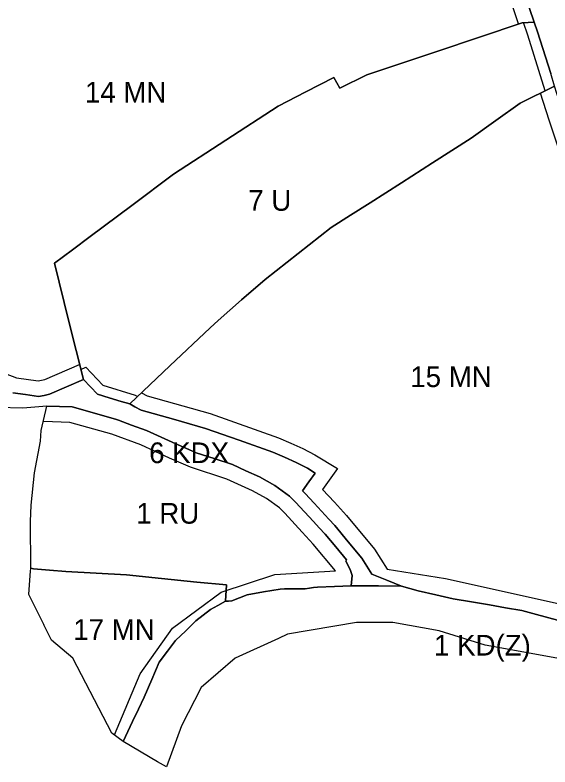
# Model space of a CAD drawing. Extents: x 7423691 to 7425475, y 5552085 to 5554331.
# Drawn here: x 7424385.3 to 7424592.3, y 5552093.8 to 5552384.7 of the extents above; entities that cross this region are included whole.
import ezdxf

# ---------------------------------------------------------------- set-up
doc = ezdxf.new("R2010")
doc.units = 0
for name, color, linetype in [('linia_zabudowy_nieprzekraczalna', 7, 'Continuous'), ('linie_rozgraniczajace', 7, 'Continuous'), ('oznaczenia_przeznaczen', 7, 'Continuous')]:
    doc.layers.add(name, color=color, linetype=linetype)

msp = doc.modelspace()

# ---------------------------------------------------------------- linework, layer by layer
at = {"layer": 'linia_zabudowy_nieprzekraczalna'}
for points in [[(7424580.08, 5552381.26), (7424571.92, 5552405.53), (7424568.75, 5552420), (7424566.65, 5552434.46), (7424566.31, 5552447.41)], [(7424590.45, 5552355.4), (7424583.65, 5552376.93), (7424582.03, 5552381.75)], [(7424597.86, 5552326.15), (7424591.95, 5552344), (7424588.63, 5552354.51)], [(7424283.11, 5552322.72), (7424290.92, 5552313.42), (7424297.88, 5552305.19), (7424302.65, 5552302.46), (7424313.35, 5552292.4), (7424329.92, 5552277.7), (7424344.76, 5552265.77), (7424358.71, 5552257.06), (7424378.55, 5552246.99), (7424385.8, 5552244.36), (7424394.2, 5552243.19), (7424396.85, 5552243.7), (7424410.23, 5552249.51)], [(7424410.72, 5552247.54), (7424412.64, 5552248.38), (7424419.3, 5552241.49), (7424431.7, 5552237.64), (7424432.69, 5552237.1)], [(7424434.22, 5552238.55), (7424436.36, 5552237.4), (7424460.83, 5552230.47), (7424487.2, 5552221.15), (7424491.95, 5552219.02), (7424496.63, 5552216.92), (7424501.31, 5552214.58), (7424510.07, 5552209.17), (7424504.24, 5552201.15), (7424508.89, 5552196.17), (7424513.53, 5552191.05), (7424524.32, 5552178.07), (7424529.22, 5552170.29), (7424551.84, 5552166.71), (7424604.77, 5552154.87)], [(7424423.7, 5552106.15), (7424433.65, 5552129.8), (7424446.15, 5552147.47), (7424465.09, 5552161.34), (7424485.81, 5552168.18), (7424509.22, 5552169.64), (7424500.69, 5552179.91), (7424496.38, 5552184.66), (7424489.61, 5552191.91), (7424487.56, 5552193.98), (7424482.6, 5552197.61), (7424477.2, 5552200.61), (7424467.19, 5552205.15), (7424453.21, 5552209.71), (7424444.98, 5552213.27), (7424433.89, 5552218.33), (7424422.67, 5552222.46), (7424406.49, 5552227.07), (7424396.44, 5552227.36)]]:
    msp.add_lwpolyline(points, dxfattribs=at)
at = {"layer": 'linie_rozgraniczajace'}
for points in [[(7424582.58, 5552392.65), (7424586.19, 5552381.92), (7424581.46, 5552381.72), (7424564.97, 5552376.16), (7424548.48, 5552370.59), (7424534.94, 5552366.09), (7424521.41, 5552361.59), (7424510.91, 5552356.36), (7424508.62, 5552360.49), (7424497.84, 5552354.96), (7424487.05, 5552349.43), (7424466.85, 5552336.28), (7424446.64, 5552323.12), (7424430.51, 5552311.05), (7424414.38, 5552298.99), (7424407.45, 5552293.8), (7424400.52, 5552288.62), (7424406.11, 5552266.11), (7424411.7, 5552243.61), (7424405.17, 5552240.77), (7424398.64, 5552237.93), (7424396.5, 5552237.52), (7424394.36, 5552237.11), (7424389.35, 5552237.81), (7424384.35, 5552238.5)], [(7424625.63, 5552277.57), (7424621.01, 5552289.31), (7424617.02, 5552298.21), (7424613.04, 5552307.12), (7424610.69, 5552312.66), (7424608.35, 5552318.19), (7424605.89, 5552323.3), (7424603.43, 5552328.4), (7424600.55, 5552337.13), (7424597.66, 5552345.85), (7424594.08, 5552357.17), (7424592.55, 5552362.01), (7424587.45, 5552378.17), (7424586.19, 5552381.92), (7424582.58, 5552392.65)], [(7424594.08, 5552357.17), (7424580.69, 5552350.62), (7424571.25, 5552343.86), (7424561.82, 5552337.09), (7424554.34, 5552332.32), (7424546.87, 5552327.54), (7424534.75, 5552319.8), (7424522.64, 5552312.06), (7424515.1, 5552307.25), (7424507.57, 5552302.44), (7424494.83, 5552292.42), (7424482.09, 5552282.4), (7424472.96, 5552274.44), (7424463.83, 5552266.48), (7424460.82, 5552263.67), (7424445.22, 5552248.94), (7424429.63, 5552234.21), (7424426.31, 5552235.2), (7424421.73, 5552236.58), (7424417.16, 5552237.95), (7424414.43, 5552240.78), (7424411.7, 5552243.61), (7424406.11, 5552266.11), (7424400.52, 5552288.62), (7424407.45, 5552293.8), (7424414.38, 5552298.99), (7424430.51, 5552311.05), (7424446.64, 5552323.12), (7424466.85, 5552336.28), (7424487.05, 5552349.43), (7424497.84, 5552354.96), (7424508.62, 5552360.49), (7424510.91, 5552356.36), (7424521.41, 5552361.59), (7424534.94, 5552366.09), (7424548.48, 5552370.59), (7424564.97, 5552376.16), (7424581.46, 5552381.72), (7424586.19, 5552381.92), (7424587.45, 5552378.17), (7424592.55, 5552362.01)], [(7424595.13, 5552150.56), (7424586.99, 5552152.73), (7424584.17, 5552153.48), (7424581.36, 5552154.23), (7424575.11, 5552155.36), (7424568.87, 5552156.5), (7424561.87, 5552157.66), (7424554.86, 5552158.81), (7424548.08, 5552160.38), (7424541.3, 5552161.95), (7424538.07, 5552162.85), (7424534.84, 5552163.75), (7424529.1, 5552166.04), (7424523.36, 5552168.32), (7424519.45, 5552174.54), (7424514.23, 5552180.83), (7424509, 5552187.12), (7424506.74, 5552189.61), (7424501.01, 5552195.82), (7424497.53, 5552199.54), (7424496.44, 5552200.63), (7424498.93, 5552204.05), (7424501.41, 5552207.46), (7424498.38, 5552209.33), (7424494.06, 5552211.5), (7424489.49, 5552213.55), (7424484.97, 5552215.57), (7424471.99, 5552220.16), (7424459.02, 5552224.75), (7424446.55, 5552228.28), (7424434.09, 5552231.8), (7424431.66, 5552233.11), (7424429.63, 5552234.21), (7424445.22, 5552248.94), (7424460.82, 5552263.67), (7424463.83, 5552266.48), (7424472.96, 5552274.44), (7424482.09, 5552282.4), (7424494.83, 5552292.42), (7424507.57, 5552302.44), (7424515.1, 5552307.25), (7424522.64, 5552312.06), (7424534.75, 5552319.8), (7424546.87, 5552327.54), (7424554.34, 5552332.32), (7424561.82, 5552337.09), (7424571.25, 5552343.86), (7424580.69, 5552350.62), (7424594.08, 5552357.17)], [(7424384.35, 5552238.5), (7424389.35, 5552237.81), (7424394.36, 5552237.11), (7424396.5, 5552237.52), (7424398.64, 5552237.93), (7424405.17, 5552240.77), (7424411.7, 5552243.61), (7424414.43, 5552240.78), (7424417.16, 5552237.95), (7424421.73, 5552236.58), (7424426.31, 5552235.2), (7424429.63, 5552234.21), (7424431.66, 5552233.11), (7424434.09, 5552231.8), (7424446.55, 5552228.28), (7424459.02, 5552224.75), (7424471.99, 5552220.16), (7424484.97, 5552215.57), (7424489.49, 5552213.55), (7424494.06, 5552211.5), (7424498.38, 5552209.33), (7424501.41, 5552207.46), (7424498.93, 5552204.05), (7424496.44, 5552200.63), (7424497.53, 5552199.54), (7424501.01, 5552195.82), (7424506.74, 5552189.61), (7424509, 5552187.12), (7424514.23, 5552180.83), (7424519.45, 5552174.54), (7424523.36, 5552168.32), (7424529.1, 5552166.04), (7424534.84, 5552163.75), (7424525.92, 5552163.82), (7424517, 5552163.89), (7424515.3, 5552163.82), (7424515.72, 5552167.87), (7424514.93, 5552170.19), (7424513.21, 5552173.32), (7424513.5, 5552173.88), (7424509.36, 5552178.86), (7424505.22, 5552183.84), (7424503.01, 5552186.28), (7424500.8, 5552188.72), (7424493.81, 5552196.2), (7424491.48, 5552198.54), (7424485.84, 5552202.67), (7424482.87, 5552204.32), (7424479.9, 5552205.97), (7424474.63, 5552208.36), (7424469.36, 5552210.75), (7424462.35, 5552213.04), (7424455.34, 5552215.32), (7424451.38, 5552217.04), (7424447.46, 5552218.74), (7424436.17, 5552223.88), (7424430.35, 5552226.02), (7424425.29, 5552227.89), (7424424.53, 5552228.16), (7424415.97, 5552230.6), (7424407.41, 5552233.04), (7424397.53, 5552233.33), (7424388.34, 5552232.59), (7424378.48, 5552232.85)], [(7424427.06, 5552103.61), (7424428.91, 5552107.49), (7424430.75, 5552111.36), (7424433, 5552116.08), (7424435.25, 5552120.81), (7424438.17, 5552127.57), (7424441.09, 5552134.34), (7424444.21, 5552138.51), (7424447.34, 5552142.68), (7424451.3, 5552146.48), (7424455.26, 5552150.28), (7424458.05, 5552152.49), (7424460.85, 5552154.7), (7424463.69, 5552156.27), (7424466.66, 5552157.85), (7424467.82, 5552157.91), (7424469.11, 5552157.98), (7424472.11, 5552159.13), (7424475.11, 5552160.29), (7424481.47, 5552161.45), (7424487.83, 5552162.6), (7424489.53, 5552162.64), (7424491.24, 5552162.67), (7424491.68, 5552162.62), (7424494.59, 5552162.64), (7424496.41, 5552162.65), (7424497.49, 5552162.66), (7424499.15, 5552162.94), (7424500.8, 5552163.23), (7424502.36, 5552163.29), (7424508.9, 5552163.56), (7424515.3, 5552163.82), (7424517, 5552163.89), (7424525.92, 5552163.82), (7424534.84, 5552163.75), (7424538.07, 5552162.85), (7424541.3, 5552161.95), (7424548.08, 5552160.38), (7424554.86, 5552158.81), (7424561.87, 5552157.66), (7424568.87, 5552156.5), (7424575.11, 5552155.36), (7424581.36, 5552154.23), (7424584.17, 5552153.48), (7424586.99, 5552152.73), (7424595.13, 5552150.56)], [(7424664.3, 5552112.25), (7424650.8, 5552112.27), (7424640.17, 5552118.07), (7424622.53, 5552125.65), (7424599.18, 5552135.12), (7424567.14, 5552140.87), (7424549.35, 5552146.45), (7424531.46, 5552149.64), (7424517.45, 5552149.68), (7424490.76, 5552145.07), (7424487.25, 5552143.48), (7424470.4, 5552135.88), (7424457.35, 5552124.46), (7424449.66, 5552109.7), (7424443.85, 5552093.75), (7424440.45, 5552095.75), (7424427.06, 5552103.61)]]:
    msp.add_lwpolyline(points, dxfattribs=at)
for points in [[(7424391.34, 5552170.61), (7424391.22, 5552188.71), (7424391.55, 5552194.98), (7424392.82, 5552207.5), (7424395.06, 5552219.76), (7424395.39, 5552223.99), (7424397.53, 5552233.33), (7424407.41, 5552233.04), (7424415.97, 5552230.6), (7424424.53, 5552228.16), (7424425.29, 5552227.89), (7424430.35, 5552226.02), (7424436.17, 5552223.88), (7424447.46, 5552218.74), (7424451.38, 5552217.04), (7424455.34, 5552215.32), (7424462.35, 5552213.04), (7424469.36, 5552210.75), (7424474.63, 5552208.36), (7424479.9, 5552205.97), (7424482.87, 5552204.32), (7424485.84, 5552202.67), (7424491.48, 5552198.54), (7424493.81, 5552196.2), (7424500.8, 5552188.72), (7424503.01, 5552186.28), (7424505.22, 5552183.84), (7424509.36, 5552178.86), (7424513.5, 5552173.88), (7424513.21, 5552173.32), (7424514.93, 5552170.19), (7424515.72, 5552167.87), (7424515.3, 5552163.82), (7424508.9, 5552163.56), (7424502.36, 5552163.29), (7424500.8, 5552163.23), (7424499.15, 5552162.94), (7424497.49, 5552162.66), (7424496.41, 5552162.65), (7424494.59, 5552162.64), (7424491.68, 5552162.62), (7424491.24, 5552162.67), (7424489.53, 5552162.64), (7424487.83, 5552162.6), (7424481.47, 5552161.45), (7424475.11, 5552160.29), (7424472.11, 5552159.13), (7424469.11, 5552157.98), (7424467.82, 5552157.91), (7424466.66, 5552157.85), (7424467.09, 5552164.28), (7424455.64, 5552165.22), (7424442, 5552166.66), (7424428.36, 5552168.1), (7424416.61, 5552168.76), (7424404.87, 5552169.41), (7424398.65, 5552169.88), (7424392.44, 5552170.36)], [(7424390.55, 5552160.42), (7424391.29, 5552169.68), (7424391.35, 5552170.44), (7424391.34, 5552170.61), (7424392.44, 5552170.36), (7424398.65, 5552169.88), (7424404.87, 5552169.41), (7424416.61, 5552168.76), (7424428.36, 5552168.1), (7424442, 5552166.66), (7424455.64, 5552165.22), (7424467.09, 5552164.28), (7424466.66, 5552157.85), (7424463.69, 5552156.27), (7424460.85, 5552154.7), (7424458.05, 5552152.49), (7424455.26, 5552150.28), (7424451.3, 5552146.48), (7424447.34, 5552142.68), (7424444.21, 5552138.51), (7424441.09, 5552134.34), (7424438.17, 5552127.57), (7424435.25, 5552120.81), (7424433, 5552116.08), (7424430.75, 5552111.36), (7424428.91, 5552107.49), (7424427.06, 5552103.61), (7424422.75, 5552106.88), (7424407.68, 5552135.79), (7424399.43, 5552142.81), (7424396.56, 5552148.5), (7424396.41, 5552148.81)]]:
    msp.add_lwpolyline(points, close=True, dxfattribs=at)

# ---------------------------------------------------------------- texts
at = {"layer": 'oznaczenia_przeznaczen'}
for s, p in [('14 MN', (7424412.3, 5552350.83)), ('7 U', (7424475.52, 5552308.95)), ('15 MN', (7424538.22, 5552240.73)), ('6 KDX', (7424437.15, 5552211.32)), ('1 RU', (7424432.17, 5552187.88)), ('17 MN', (7424407.79, 5552142.91)), ('1 KD(Z)', (7424547.41, 5552136.86))]:
    msp.add_text(s, height=8, dxfattribs=at).set_placement(p)

doc.saveas('drawing.dxf')
